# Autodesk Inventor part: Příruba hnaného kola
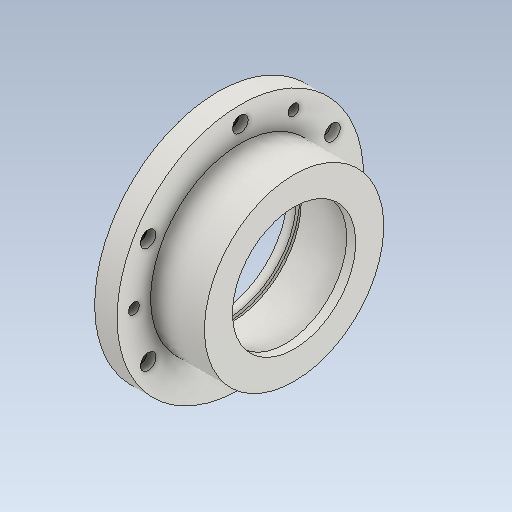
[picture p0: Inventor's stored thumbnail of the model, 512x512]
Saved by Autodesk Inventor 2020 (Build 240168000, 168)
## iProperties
Created: 2025-03
Part Number: Příruba hnaného kola
Material: Ocel
Document SubType Name: Modeling
Designer: doma
Density: 7.85 g/cm^3
Appearance: Ocel
Mass: 863.791 g
Surface Area: 325.554 cm^2
Volume: 110.037 cm^3
Author: doma
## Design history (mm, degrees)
sketch "Náčrt1"
  geometry: L1 (0, 0)-(22.076, 0) reference; L2 (0, 55)-(-10, 55); L3 (-10, 55)-(-10, 31); L4 (-10, 31)-(-5.95, 31); L5 (-5.95, 31)-(-5.95, 32.5); L6 (-5.95, 32.5)-(-3.8, 32.5); L7 (-3.8, 32.5)-(-3.8, 31); L8 (24, 31)-(24, 40); L9 (24, 40)-(0, 40); L10 (0, 40)-(0, 55); L11 (-3.8, 31)-(20, 31); L12 (20, 31)-(20, 27.5); L13 (20, 27.5)-(24, 27.5); L14 (24, 27.5)-(24, 31); L15 (0, 9.877)-(-3, 9.877); L16 (0, 9.877)-(17, 9.877); L17 (17, 9.877)-(17, 57.127); L18 (-3, 9.877)-(-3, 68.693)
  constraints: 36 end point, 10 perpendicular, 7 horizontal, 2 point on line, 1 vertical
  dimensions: "d0" = 10 distance of L2.start L2.end; "d1" = 55 distance between parallel lines of L1 L2; "d2" = 31 distance from line of L1 L3.end; "d4" = 40 distance between parallel lines of L9 L1; "d6" = 4 distance of L12.end L13.end; "d7" = 23.8 distance of L7.end L11.end; "d8" = 32.5 distance from line of L1.start L6; "d9" = 2.15 distance of L5.end L6.end; "d11" = 27.5 distance between parallel lines of L1 L13; "d12" = 24 distance of L8.end L9.end; "d37" = 3 distance of L15.start L15.end; "d38" = 17 distance of L15.start L16.end
revolve "Rotace1" sketch "Náčrt1" stored, may be unused: angle "d13" = 90 deg
sketch "Náčrt2"
  geometry: 7 further points
  constraints: 7 other
  dimensions: "d14" = 47.5 distance of point (0, 47.5) point (0, 0); "d17" = 360 deg dimension on point (0, 0) point (0, 47.5) (derived)
hole "Díra1" sketch "Náčrt2" at (0, 47.5), (-41.136, 23.75), (-41.136, -23.75), (0, -47.5), (41.136, -23.75), (41.136, 23.75) diameter "d19" = 7; stored, may be unused: countersink angle "d23" = 90 deg, drill point angle "d25" = 118 deg; dims "d20" = 12, "d21" = 11, "d22" = 6, "d24" = 8
sketch "Náčrt3"
  geometry: C1 r 5.5 at (0, 47.5) reference; A1 r 47.5 centre (0, 0) between (0, 47.5) and (47.5, 0); 3 further points
  constraints: 2 point on circle, 1 centre point, 1 coincident, 4 other
  dimensions: "d28" = 360 deg dimension on point (0, 0) A1.end (derived)
hole "Díra2" sketch "Náčrt3" at (47.5, 0), (-23.75, 41.136), (-23.75, -41.136) diameter "d30" = 4.917; stored, may be unused: countersink angle "d34" = 90 deg, drill point angle "d36" = 118 deg; dims "d31" = 12, "d32" = 11, "d33" = 6, "d35" = 17.1
node "Těleso1"
